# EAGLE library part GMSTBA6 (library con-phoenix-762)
PHOENIX
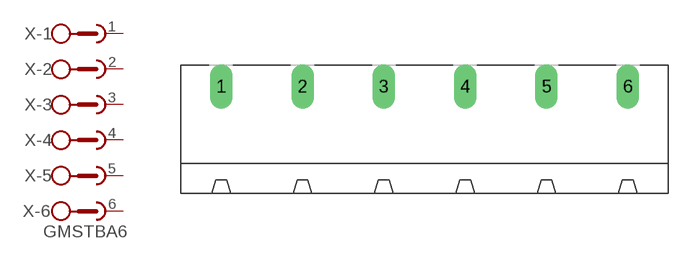
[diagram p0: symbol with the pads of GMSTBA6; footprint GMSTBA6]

Designator prefix X; gates -1=SKB -2=SKB -3=SKB -4=SKB -5=SKB -6=SKBV

## GMSTBA6 (MF: FARNELL; MPN: 1757284; OC_FARNELL: 3705213; OC_NEWARK: 71C4165)  [GMSTBA6]
1  -1:1  pas
2  -2:1  pas
3  -3:1  pas
4  -4:1  pas
5  -5:1  pas
6  -6:1  pas

## Footprint GMSTBA6 (pad centres in mm)
PHOENIX
drill 1.397 long: 1 -19.05,5.08; 2 -11.43,5.08; 3 -3.81,5.08; 4 3.81,5.08; 5 11.43,5.08; 6 19.05,5.08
